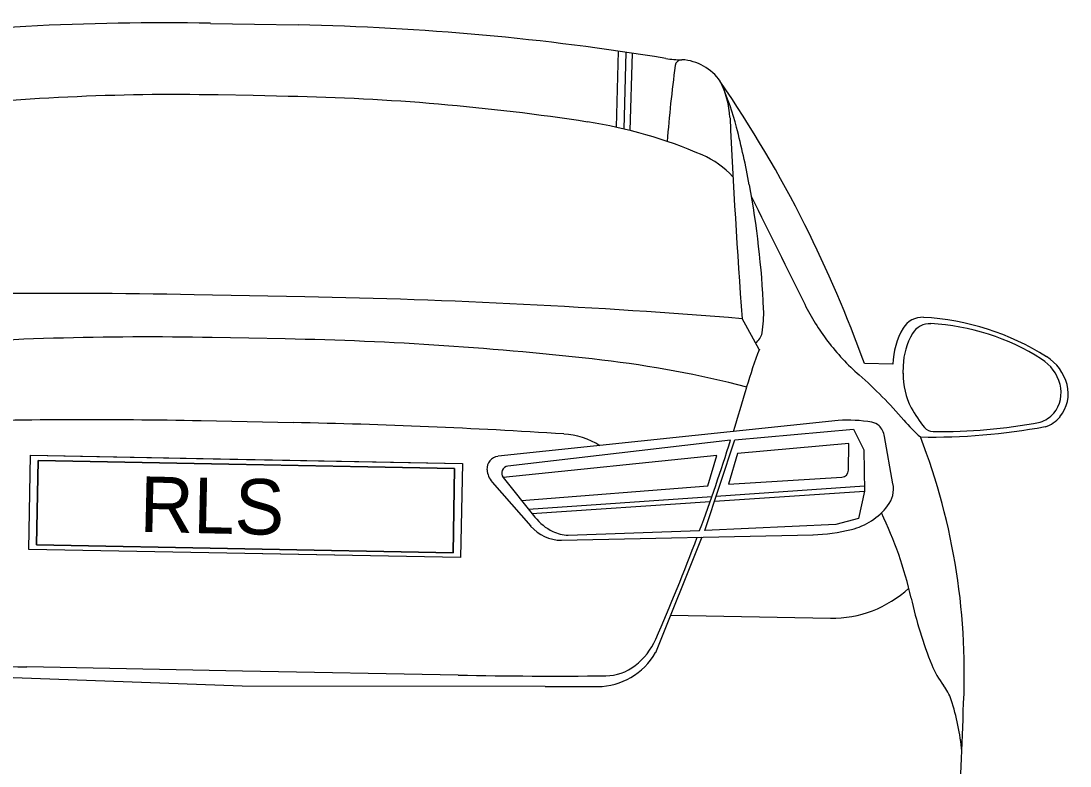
# Model space of a CAD drawing. Extents: x 10133 to 81668, y 4692 to 11018.
# Drawn here: x 30185.6 to 30291.6, y 6849.7 to 6925 of the extents above; entities that cross this region are included whole.
import ezdxf

# ---------------------------------------------------------------- set-up
doc = ezdxf.new("R2010")
doc.units = 0
doc.layers.add('Cell', color=7, linetype='Continuous')
doc.layers.add('SheetBorder', color=7, linetype='Continuous')

msp = doc.modelspace()

# ---------------------------------------------------------------- linework, layer by layer
at = {"layer": 'Cell'}
for p, q in [((30245.77, 6914.26), (30245.99, 6921.96)), ((30246.55, 6914.08), (30246.77, 6921.85)), ((30247.16, 6913.93), (30247.38, 6921.76)), ((30260.22, 6891.8), (30258.47, 6894.91)), ((30273.73, 6890.31), (30270.86, 6890.37)), ((30274.76, 6889.38), (30274.78, 6890.14)), ((30268.19, 6884.6), (30233.8, 6880.99)), ((30257.31, 6882.61), (30234.8, 6880)), ((30273.73, 6878.22), (30272.88, 6883)), ((30186.36, 6871.58), (30186.53, 6881.09)), ((30186.53, 6881.09), (30208.36, 6880.67)), ((30187.29, 6880.55), (30187.14, 6872.04)), ((30208.35, 6880.15), (30187.29, 6880.55)), ((30208.36, 6880.67), (30230.2, 6880.26)), ((30229.41, 6879.75), (30208.35, 6880.15)), ((30229.26, 6871.24), (30229.41, 6879.75)), ((30230.2, 6880.26), (30230.02, 6870.75)), ((30233.2, 6878.39), (30237.11, 6873.94)), ((30234.33, 6878.84), (30237.52, 6874.85)), ((30257.11, 6878.17), (30268.56, 6878.87)), ((30255.69, 6876.45), (30270.85, 6877.46)), ((30255.86, 6876.97), (30270.84, 6878.02)), ((30236.89, 6875.64), (30255.43, 6876.94)), ((30237.23, 6875.22), (30255.24, 6876.42)), ((30240.23, 6872.51), (30265.65, 6873.06)), ((30240.88, 6873.02), (30254.18, 6873.48)), ((30187.14, 6872.04), (30208.2, 6871.64)), ((30254.42, 6872.81), (30249.71, 6861.13)), ((30208.19, 6871.17), (30186.36, 6871.58)), ((30230.02, 6870.75), (30208.19, 6871.17)), ((30208.2, 6871.64), (30229.26, 6871.24)), ((30251.25, 6864.94), (30267.41, 6864.63))]:
    msp.add_line(p, q, dxfattribs=at)
for points in [[(30204.74, 6924.77), (30209.17, 6924.69), (30213.61, 6924.61)], [(30212.59, 6917.39), (30209.04, 6917.46), (30205.49, 6917.53)], [(30214.26, 6897.11), (30208.67, 6897.22), (30203.07, 6897.32)], [(30212.28, 6892.86), (30208.59, 6892.93), (30204.9, 6893)], [(30213.09, 6884.39), (30208.43, 6884.48), (30203.78, 6884.57)], [(30254.71, 6873.5), (30257.74, 6882.66), (30269.75, 6883.73), (30270.77, 6881.65), (30270.85, 6877.46), (30270.25, 6874.7), (30267.97, 6874.09), (30254.71, 6873.5)], [(30269.22, 6879.57), (30269.27, 6882.27), (30258.01, 6881.29), (30257.11, 6878.17)], [(30236.19, 6876.51), (30255.02, 6878.01), (30255.93, 6881.07), (30234.33, 6878.84)], [(30229.77, 6858.86), (30207.97, 6859.28), (30186.17, 6859.69)], [(30238.56, 6857.7), (30207.94, 6857.74), (30177.34, 6858.86)]]:
    msp.add_lwpolyline(points, dxfattribs=at)
for centre, major_axis, start_param, end_param in [((30199.82, 6657.17), (0.78, -267.65), 3.120007, 3.261498), ((30208.69, 6657), (0.78, -267.65), 2.978516, 3.120007), ((30252.45, 6931.84), (0.03, -10.76), 6.120109, 6.27416), ((30252.39, 6920.4), (0.002, -0.689), 3.140474, 4.570017), ((30252.11, 6915.94), (0.01, -5.16), 2.182411, 3.08264), ((30369, 6903.79), (0.35, -120.12), 4.570017, 4.634219), ((30248.6, 6914.82), (0.03, -8.78), 1.615314, 2.053089), ((30152.23, 6845.73), (0.37, -128.41), 2.042534, 2.174295), ((30201.17, 6682.47), (0.68, -235.1), 3.120007, 3.251156), ((30229.99, 6906.79), (0.09, -29.29), 1.825549, 1.979981), ((30208.27, 6682.33), (0.68, -235.1), 2.988858, 3.120007), ((30235.77, 6867.15), (0.14, -48.19), 2.734832, 2.988858), ((31002.61, 6951.08), (2.2, -756.85), 4.756907, 4.783813), ((30177.67, 6892.81), (0.24, -84.17), 1.754888, 1.825549), ((30250.79, 6902.8), (0.03, -9.42), 2.323499, 2.734832), ((30173.14, 6891.94), (0.26, -88.85), 1.612544, 1.754888), ((32145.6, 7861.37), (6.21, -2137.91), 5.172147, 5.177831), ((30142.7, 6842.17), (0.4, -138.64), 1.922977, 2.033504), ((30189.53, 6160.34), (2.14, -737.12), 3.120007, 3.180922), ((30200.72, 6160.12), (2.14, -737.12), 3.059092, 3.120007), ((30285.55, 6907.01), (0.07, -23.58), 5.177831, 5.364919), ((30249.6, 6895.4), (0.03, -11.22), 1.396134, 1.612544), ((30276.69, 6892.76), (0.01, -2.29), 3.083943, 4.165968), ((30277.45, 6892.34), (0.01, -2.06), 3.083943, 4.165968), ((30275.38, 6868.39), (0.08, -26.69), 2.582762, 3.083943), ((30276.26, 6870.41), (0.07, -24.03), 2.582762, 3.083943), ((30198.55, 6547.3), (1, -345.76), 3.120007, 3.214195), ((30258.96, 6893.75), (0, -1.58), 0.60517, 1.396134), ((30280.91, 6890.18), (0.02, -7.28), 4.165968, 4.690803), ((30281.24, 6890.02), (0.02, -6.56), 4.165968, 4.690803), ((30205.92, 6547.16), (1, -345.76), 3.025819, 3.120007), ((30285.08, 6906.64), (0.07, -22.97), 5.364919, 5.570378), ((30299.15, 6876.16), (0.12, -42.47), 4.332271, 4.426951), ((30286.77, 6887), (0.01, -4.79), 1.830697, 2.582762), ((30232.03, 6780.85), (0.32, -110.57), 2.889231, 3.025819), ((30286.52, 6887.15), (0.01, -4.31), 1.830697, 2.582762), ((30242.24, 6856.08), (0.13, -43.69), 2.280619, 2.428785), ((30281.84, 6889.25), (0.02, -7.18), 4.690803, 5.195439), ((30070.16, 6943.59), (0.58, -199.38), 1.261729, 1.285358), ((30287.55, 6887.43), (0.01, -3.23), 0.868626, 1.830697), ((30287.91, 6887.31), (0.01, -3.59), 0.868626, 1.830697), ((30284.87, 6890.87), (0.03, -10.65), 5.195439, 5.421454), ((30192.39, 6264.99), (1.8, -619.69), 3.120007, 3.16484), ((30269.18, 6869.01), (0.05, -15.63), 2.980494, 3.202621), ((30287.79, 6887.22), (0.01, -2.9), 0.290491, 0.868626), ((30288.19, 6887.07), (0.01, -3.23), 0.290491, 0.868626), ((30201.7, 6264.81), (1.8, -619.69), 3.075174, 3.120007), ((30271.41, 6883.11), (0, -1.34), 2.379945, 2.993447), ((30270.88, 6882.64), (0.01, -2.06), 1.746734, 2.350337), ((30287.21, 6895.5), (0.05, -16.6), 5.422211, 5.567254), ((30277.83, 6945.52), (0.18, -62.58), 6.258811, 6.464055), ((30277.81, 6884.7), (0, -1.2), 5.421454, 6.268082), ((30278.47, 6939.82), (0.16, -56.33), 6.268082, 6.464055), ((30239.95, 6875.28), (0.02, -7.98), 2.584625, 3.075174), ((30070.16, 6943.59), (0.58, -199.38), 1.208619, 1.257099), ((30216.37, 6859.09), (0.19, -65.5), 1.508257, 1.940781), ((30233.92, 6879.73), (0, -1.26), 3.241933, 4.787449), ((30234.77, 6879.8), (0.01, -2.12), 4.787449, 5.436302), ((30234.88, 6879.29), (0.002, -0.718), 3.252454, 5.39193), ((30268.52, 6879.59), (0.002, -0.718), 0.057242, 1.549211), ((30271.03, 6877.7), (0.01, -2.79), 0.898902, 1.75794), ((30267.93, 6880.19), (0.02, -6.8), 0.238642, 0.898902), ((30238.68, 6858.26), (0.11, -38.34), 1.788873, 2.027372), ((30241.68, 6878.28), (0.02, -5.44), 5.39193, 5.826812), ((30240.24, 6876.76), (0.01, -4.26), 5.435788, 6.275832), ((30240.96, 6876.78), (0.01, -3.76), 5.826812, 6.258127), ((30265.26, 6891.16), (0.05, -18.1), 0.018579, 0.238642), ((30070.16, 6943.59), (0.58, -199.38), 1.14901, 1.204977), ((30267.63, 6876.22), (0.03, -11.59), 6.2616, 7.020005), ((30317.07, 6876.12), (0.13, -43.15), 4.930466, 5.095041), ((30243.56, 6865.28), (0.02, -6.86), 0.650241, 1.14901), ((30243.85, 6864.58), (0.02, -6.87), 0.001017, 1.042677), ((30195.98, 7393.41), (1.55, -533.81), 6.233227, 6.2616), ((30244.65, 6863.83), (0.01, -5.04), 0.006787, 0.650241), ((30285.33, 6863.06), (0.02, -8.41), 5.095041, 5.382013), ((30239.58, 7392.58), (1.55, -533.81), 6.2616, 6.289972), ((30239.86, 7885.34), (2.99, -1027.63), 6.278956, 6.284202), ((30275.26, 6854.93), (0.01, -4.64), 1.884865, 2.240421), ((30256.73, 6848.76), (0.07, -24.43), 1.666626, 1.884865), ((30035.84, 6861.6), (0.72, -248.58), 1.491325, 1.542118)]:
    msp.add_ellipse(centre, major_axis=major_axis, ratio=0.985916, start_param=start_param, end_param=end_param, dxfattribs=at)
at = {"layer": 'SheetBorder'}
for points in [[(30186.53, 6881.09), (30230.2, 6880.26), (30230.02, 6870.75), (30186.36, 6871.58)], [(30187.29, 6880.55), (30229.41, 6879.75), (30229.26, 6871.24), (30187.14, 6872.04)]]:
    msp.add_lwpolyline(points, close=True, dxfattribs=at)

# ---------------------------------------------------------------- texts
msp.add_text('RLS', height=5.612, rotation=358.6868, dxfattribs=at).set_placement((30197.53, 6873.36))

doc.saveas('drawing.dxf')
